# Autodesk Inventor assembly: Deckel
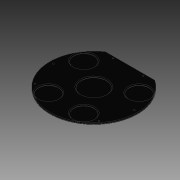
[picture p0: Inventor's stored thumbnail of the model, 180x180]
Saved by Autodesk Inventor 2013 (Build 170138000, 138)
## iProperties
Created: 2012-10
Part Number: Deckel
Document SubType Name: Assembly
Designer: SteffenHaase
Author: SteffenHaase
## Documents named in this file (4)
- D:\SVN\2013\Inventor\Gehäuse\MG-Deckel.iam
- MG-Deckel.iam
- D:\SVN\2013\Inventor\Gehäuse\Deckel A.ipt
- D:\SVN\2013\Inventor\Gehäuse\Deckel B.ipt
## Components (2 placed, 2 different names)
1. Deckel A:1 — Passend:1, Passend:2, Winkel:1
2. Deckel B:1 — Passend:1, Passend:2, Winkel:1
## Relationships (3: Mate 2, Angle 1)
- Passend:1 [Mate]: Deckel A:1 ↔ Deckel B:1
- Passend:2 [Mate]: Deckel A:1 ↔ Deckel B:1
- Winkel:1 [Angle]: Deckel A:1 ↔ Deckel B:1
